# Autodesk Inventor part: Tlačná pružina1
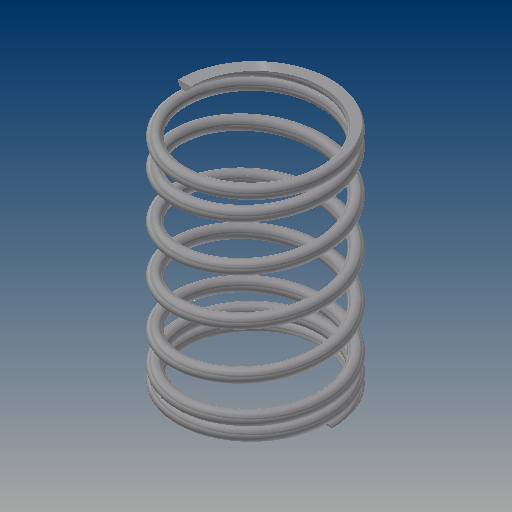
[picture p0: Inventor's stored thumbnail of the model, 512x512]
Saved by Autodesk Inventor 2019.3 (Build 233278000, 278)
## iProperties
Created: 2019-03
Part Number: Tlačná pružina1
Material: Steel
Document SubType Name: Modeling
Designer: B-hon
Density: 2.18 g/cm^3
Appearance: Steel
CustomPartVersion: 1
Author: B-hon
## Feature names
1. Main Coil Feature(R)
2. Počáteční přechodová spirála 1 (pravá)
3. Coil  Start Transition 2(R)
4. Coil  Start Transition 3(R)
5. Coil  Start Transition 4(R)
6. Spirála počátečních ukončení (pravá)
7. Prvek počátečního řezu (pravý) [Extrusion]
8. Koncová přechodová spirála 1 (pravá)
9. Koncová přechodová spirála 2 (pravá)
10. Koncová přechodová spirála 3 (pravá)
11. Koncová přechodová spirála 4 (pravá)
12. Koncová spirála (pravá)
13. Prvek koncového řezu (pravý) [Extrusion]
14. Prvek řezu rovných konců 1 (pravý) [Extrusion]
15. Plain Ends Cut  2(R) [Extrusion]
16. Main Coil Feature(L)
17. Počáteční přechodová spirála 1 (levá)
18. Počáteční přechodová spirála 2 (levá)
19. Počáteční přechodová spirála 3 (levá)
20. Počáteční přechodová spirála 4 (levá)
21. Spirála počátečních zakončení (levá)
22. Prvek počátečního řezu (levý) [Extrusion]
23. Koncová přechodová spirála 1 (levá)
24. Koncová přechodová spirála 2 (levá)
25. Koncová přechodová spirála 3 (levá)
26. Koncová přechodová spirála 4 (levá)
27. Koncová spirála (levá)
28. Koncový prvek řezu (levý) [Extrusion]
29. Cut Plain Ends Cut 1(L) [Extrusion]
30. Cut Plain Ends Cut 2(L) [Extrusion]
## Parameters: d0 = 0.25 mm, da_d = 1 mm, da_D2 = 10.4 mm, da_ti = 3.75164 mm, da_nz1 = 15 mm, spiral_Angle = 1.04372 mm, d2 = 3.75164 mm, d4 = 32.5 mm, d5 = 0, d6 = 90 deg, d7 = 90 deg, d8 = 0, d9 = 0, d12 = 2.52391 mm, d13 = -3.28325 mm, d14 = 1 mm, d15 = 0, d16 = 3.06373 mm, d18 = 2.5 mm, d19 = 0, d20 = 90 deg, d21 = 90 deg, d22 = 0, d23 = 0, d24 = 2.37582 mm, d26 = 2.5 mm, d27 = 0, d28 = 90 deg, d29 = 90 deg, d30 = 0, d31 = 0, d32 = 1.68791 mm, d34 = 2.5 mm, d35 = 0, d36 = 90 deg, d37 = 90 deg, d38 = 0, d39 = 0, d40 = 1 mm, d42 = 2.5 mm, d43 = 0, d44 = 90 deg, d45 = 90 deg, d46 = 0, d47 = 0, d48 = 3.06373 mm, d50 = 1.875 mm, d51 = 0, d52 = 90 deg, d53 = 90 deg, d54 = 0, d55 = 0, d56 = 2.37582 mm, d58 = 1.875 mm, d59 = 0, d60 = 90 deg, d61 = 90 deg, d62 = 0, d63 = 0, d64 = 1.68791 mm, d66 = 1.875 mm, d67 = 0, d68 = 90 deg, d69 = 90 deg, d70 = 0, d71 = 0, d72 = 1 mm, d74 = 1.875 mm, d75 = 0, d76 = 90 deg, d77 = 90 deg, d78 = 0, d79 = 0, End_Pitch = 1.00547 mm, d82 = 15 mm, d83 = 0, d84 = 90 deg, d85 = 90 deg, d86 = 0, d87 = 0, d88 = 1.00547 mm, d91 = 0, d92 = 90 deg, d93 = 90 deg, d94 = 0, d95 = 0, d96 = 12.4 mm, d97 = 1.00547 mm, d98 = 0, d99 = 12.4 mm, d100 = 1.00547 mm, d101 = 0, d102 = 0, d103 = 0, d104 = 0, d105 = 0, d106 = 0, d108 = 0, d112 = 0, d113 = 0, d114 = 0, const_zero = 0, Not_rightdir = 0, d121 = 0.25682 mm, d131 = 0, d132 = 0, d133 = 0, d134 = 0, d135 = 0.25 mm, d137 = 3.75164 mm, d139 = 32.5 mm, d140 = 0, d141 = 90 deg, d142 = 90 deg, d143 = 0, d144 = 0, d145 = 2.52391 mm, d146 = -3.28325 mm, d147 = 0.25682 mm, d148 = 0.00546 mm, d149 = 1 mm, d150 = 0, d151 = 0, d152 = 3.06373 mm, d154 = 2.5 mm, d155 = 0, d156 = 90 deg, d157 = 90 deg, d158 = 0, d159 = 0, d160 = 2.37582 mm, d162 = 2.5 mm, d163 = 0, d164 = 90 deg, d165 = 90 deg, d166 = 0, d167 = 0, d168 = 1.68791 mm, d170 = 2.5 mm, d171 = 0, d172 = 90 deg, d173 = 90 deg, d174 = 0, d175 = 0, d176 = 1 mm, d178 = 2.5 mm, d179 = 0, d180 = 90 deg, d181 = 90 deg, d182 = 0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
